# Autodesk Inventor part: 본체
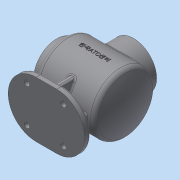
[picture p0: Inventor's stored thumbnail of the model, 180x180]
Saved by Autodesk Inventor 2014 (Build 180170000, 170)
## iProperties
Created: 2023-01
Part Number: 본체
Material: 일반
Document SubType Name: Modeling
Designer: dg
Density: 1 g/cm^3
Appearance: 기본값
Author: dg
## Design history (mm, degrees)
sketch "스케치1"
  geometry: L1 (-61, 0)-(61, 0); L2 (-61, 38)-(-49, 38); L3 (-49, 38)-(-49, 50); L4 (-49, 50)-(50.087, 50); L5 (-61, 38)-(-61, 27); L6 (-44, 27)-(-44, 45); L7 (-44, 45)-(46.83, 45); L8 (-61, 27)-(-44, 27); A1 r 120 centre (-59, 0) between (61, 0) and (50.087, 50); A2 r 115 centre (-59, 0) between (56, 0) and (46.83, 45); 2 further points
  constraints: 16 end point, 4 point on circle, 3 parallel, 2 centre point, 2 coincident, 2 perpendicular, 2 point on line, 1 horizontal, 1 midpoint, 1 vertical alignment, 2 other
  dimensions: "d0" = 122 distance of L1.start L1.end; "d1" = 100 diameter of L4 L1; "d2" = 76 diameter of L2 L1; "d4" = 120 radius of A1; "d5" = 110 distance from line of L1.end L3; "d6" = 5 radial gap between concentric circles of A1 A2; "d58" = 54 diameter of L8 L1
revolve "회전1" sketch "스케치1" stored, may be unused: angle "d7" = 90 deg
node "작업 평면1"
sketch "스케치2"
  geometry: L1 (61, 38)-(61, -38) reference; C1 r 38 at (-2, 0); C2 r 27 at (-2, 0); 1 further point
  constraints: 2 centre point, 2 coincident
  dimensions: "d9" = 76 diameter of C1; "d10" = 54 diameter of C2; "d72" = 63 distance from line of L1 point (-2, 0)
extrude "돌출1" join sketch "스케치2" stored distance "d11" = 10; taper "d12" = 0 deg
extrude "돌출2" cut sketch "스케치2" stored distance "d13" = 10; taper "d14" = 0 deg
node "작업 평면2"
sketch "스케치3"
  geometry: L1 (-61, -46)-(65, -46); L2 (65, -46)-(65, 46); L3 (65, 46)-(-61, 46); L4 (-61, 46)-(-61, -46); L5 (-61, -46)-(65, 46); L6 (65, -46)-(-61, 46); L7 (-61, -38)-(-61, 38) reference; 3 further points
  constraints: 12 end point, 3 midpoint, 2 parallel, 1 horizontal, 1 horizontal alignment, 1 perpendicular, 1 point on line
  dimensions: "d16" = 126 distance of L2.end L3.end; "d17" = 92 distance of L1.end L2.end
extrude "돌출3" join sketch "스케치3" distance "d18" = 10; taper "d19" = 0 deg
fillet "모깎기1" dims "d20" = 46
fillet "모깎기2" dims "d21" = 3
chamfer "모따기1" distance "d22" = 1; stored, may be unused: second distance "d23" = 2, angle "d24" = 45 deg
sketch "스케치6"
  geometry: C1 r 4.5 at (-30, 30); C2 r 4.5 at (30, 30); C3 r 4.5 at (-30, -30); C4 r 4.5 at (30, -30); 1 further point
  constraints: 4 centre point, 3 equal radius, 2 horizontal alignment, 2 vertical alignment
  dimensions: "d36" = 9 diameter of C1; "d37" = 30 horizontal distance of point (0, 0) C1.centre; "d38" = 30 horizontal distance of point (0, 0) C1.centre; "d70" = 30 horizontal distance of C2.centre point (0, 0); "d71" = 30 horizontal distance of point (0, 0) C3.centre
extrude "돌출5" cut sketch "스케치6" distance "d39" = 10; taper "d40" = 0 deg
fillet "모깎기3" dims "d44" = 8
sketch "스케치7"
  geometry: C1 r 28 at (0, 0) reference; 1 further point
  constraints: 1 vertical alignment
  dimensions: "d47" = 32.5 distance of C1.centre point (0, 32.5)
hole "구멍1" sketch "스케치7" at (0, 32.5) diameter "d48" = 3.242; stored, may be unused: countersink angle "d52" = 90 deg, drill point angle "d54" = 118 deg; dims "d49" = 8, "d50" = 4, "d51" = 2, "d53" = 10
sketch "스케치8"
  geometry: C1 r 38 at (0, 0) reference; 1 further point
  constraints: 1 vertical alignment
  dimensions: "d59" = 32.5 distance of C1.centre point (0, 32.5)
hole "구멍2" sketch "스케치8" at (0, 32.5) diameter "d60" = 3.242; stored, may be unused: countersink angle "d64" = 90 deg, drill point angle "d66" = 118 deg; dims "d61" = 8, "d62" = 4, "d63" = 2, "d65" = 10
node "작업 평면3"
sketch "스케치9"
  geometry: L1 (27, 63)-(28, 64) reference; L2 (28, 64)-(30.879, 64) reference; L3 (30.879, 64)-(30.879, 54) reference; L4 (30.879, 54)-(32.5, 53.026) reference; L5 (32.5, 53.026)-(34.121, 54) reference; L6 (34.121, 54)-(34.121, 64) reference; L7 (34.121, 64)-(38, 64) reference; L8 (38, 64)-(38, 33.586) reference; L9 (-38, 33.586)-(-38, 64) reference; L10 (-38, 64)-(-34.121, 64) reference; L11 (-34.121, 64)-(-34.121, 54) reference; L12 (-34.121, 54)-(-32.5, 53.026) reference; L13 (-32.5, 53.026)-(-30.879, 54) reference; L14 (-30.879, 54)-(-30.879, 64) reference; L15 (-30.879, 64)-(-28, 64) reference; L16 (-28, 64)-(-27, 63) reference; L17 (-27, 63)-(-27, 36) reference; L18 (27, 36)-(27, 63) reference; L19 (46, -73)-(46, -80) reference; L20 (46, -80)-(-46, -80) reference; L21 (-46, -80)-(-46, -73) reference; L22 (-43, -70)-(43, -70) reference; L23 (-35, -35.707)-(-35, -70); L24 (-35, -70)-(35, -70); L25 (35, -70)-(35, -35.707); A1 r 50 centre (0, 0) between (-38.679, 31.685) and (38.679, 31.685) reference; A2 r 45 centre (0, 0) between (-27, 36) and (27, 36) reference; A3 r 3 centre (43, -73) between (46, -73) and (43, -70) reference; A4 r 3 centre (-43, -73) between (-43, -70) and (-46, -73) reference; 2 further points
  constraints: 6 end point, 2 perpendicular, 2 point on circle, 2 point on line, 1 midpoint, 1 parallel, 1 vertical alignment, 2 other
  dimensions: "d74" = 35 distance from line of point (0, 0) L23
extrude "돌출6" join sketch "스케치9" stored distance "d75" = 10; taper "d76" = 0 deg
sketch "스케치10"
  geometry: L1 (-41, -45)-(44.827, -45) reference; L2 (44.827, 45)-(29, 45) reference; L3 (29, 45)-(29, 63) reference; L4 (29, 63)-(30, 64) reference; L5 (30, 64)-(32.879, 64) reference; L6 (32.879, 64)-(32.879, 54) reference; L7 (32.879, 54)-(34.5, 53.026) reference; L8 (34.5, 53.026)-(36.121, 54) reference; L9 (36.121, 54)-(36.121, 64) reference; L10 (36.121, 64)-(40, 64) reference; L11 (40, 64)-(40, 53) reference; L12 (43, 50)-(44.827, 50) reference; L13 (44.827, -50)-(7, -50) reference; L14 (7, -50)-(7, -70) reference; L15 (7, -70)-(62, -70) reference; L16 (65, -73)-(65, -80) reference; L17 (65, -80)-(-61, -80) reference; L18 (-61, -80)-(-61, -73) reference; L19 (-58, -70)-(-3, -70) reference; L20 (-3, -70)-(-3, -50) reference; L21 (-3, -50)-(-41, -50) reference; L22 (-49, -42)-(-49, -41) reference; L23 (-52, -38)-(-61, -38) reference; L24 (-61, -38)-(-61, -34.121) reference; L25 (-61, -34.121)-(-51, -34.121) reference; L26 (-51, -34.121)-(-50.026, -32.5) reference; L27 (-50.026, -32.5)-(-51, -30.879) reference; L28 (-51, -30.879)-(-61, -30.879) reference; L29 (-61, -30.879)-(-61, -28) reference; L30 (-61, -28)-(-60, -27) reference; L31 (-60, -27)-(-44, -27) reference; L32 (-44, -27)-(-44, -42) reference; L33 (-44, 42)-(-44, 27) reference; L34 (-44, 27)-(-60, 27) reference; L35 (-60, 27)-(-61, 28) reference; L36 (-61, 28)-(-61, 30.879) reference; L37 (-61, 30.879)-(-51, 30.879) reference; L38 (-51, 30.879)-(-50.026, 32.5) reference; L39 (-50.026, 32.5)-(-51, 34.121) reference; L40 (-51, 34.121)-(-61, 34.121) reference; L41 (-61, 34.121)-(-61, 38) reference; L42 (-61, 38)-(-52, 38) reference; L43 (-49, 41)-(-49, 42) reference; L44 (-41, 50)-(-39, 50) reference; L45 (-36, 53)-(-36, 64) reference; L46 (-36, 64)-(-32.121, 64) reference; L47 (-32.121, 64)-(-32.121, 54) reference; L48 (-32.121, 54)-(-30.5, 53.026) reference; L49 (-30.5, 53.026)-(-28.879, 54) reference; L50 (-28.879, 54)-(-28.879, 64) reference; L51 (-28.879, 64)-(-26, 64) reference; L52 (-26, 64)-(-25, 63) reference; L53 (-25, 63)-(-25, 45) reference; L54 (-25, 45)-(-41, 45) reference; L55 (-38, -70)-(-32.641, -50); A1 r 3 centre (-41, -42) between (-44, -42) and (-41, -45) reference; A2 r 3 centre (44.827, -42) between (44.827, -45) and (47.608, -43.125) reference; A3 r 115 centre (-59, 0) between (47.608, -43.125) and (47.608, 43.125) reference; A4 r 3 centre (44.827, 42) between (47.608, 43.125) and (44.827, 45) reference; A5 r 8 centre (44.827, 42) between (52.243, 45) and (44.827, 50) reference; A6 r 120 centre (-59, 0) between (52.243, -45) and (52.243, 45) reference; A7 r 8 centre (44.827, -42) between (44.827, -50) and (52.243, -45) reference; A8 r 3 centre (62, -73) between (65, -73) and (62, -70) reference; A9 r 3 centre (-58, -73) between (-58, -70) and (-61, -73) reference; A10 r 8 centre (-41, -42) between (-49, -42) and (-41, -50) reference; A11 r 3 centre (-52, -41) between (-49, -41) and (-52, -38) reference; A12 r 3 centre (-41, 42) between (-41, 45) and (-44, 42) reference; A13 r 3 centre (-52, 41) between (-52, 38) and (-49, 41) reference; A14 r 8 centre (-41, 42) between (-41, 50) and (-49, 42) reference; 1 further point
  constraints: 2 end point, 2 point on line, 2 other
  dimensions: "d77" = 105 deg angle of L19 L55; "d78" = 23 distance from line of L18 L55.start
feature "리브2" sketch "스케치10" dims "d79" = 1, "d80" = 10, "d81" = 0, "d82" = 0, "d83" = 1, "d84" = 1
fillet "모깎기6" dims "d85" = 3
fillet "모깎기7" dims "d86" = 3
node "작업 평면4"
sketch "스케치11"
  geometry: L1 (-61.544, -38)-(-61.544, 38) reference; L2 (64.456, -80)-(18.456, -80) reference; 2 further points
  constraints: 1 other
  dimensions: "d87" = 63 distance from line of L1 point (1.456, 0); "d88" = 80 distance from line of L2 point (1.456, 0)
feature "엠보싱1" sketch "스케치11" dims "d89" = 0.5, "d90" = 0
node "솔리드1"
pattern_circular "원형 패턴1" dims angle "d56" = 360 deg
pattern_circular "원형 패턴2" dims angle "d68" = 360 deg
mirror "대칭3"
node "절단 모서리 투영4"
node "절단 모서리 투영5"
other parameters: "d8" = 64, "d73" = -63
